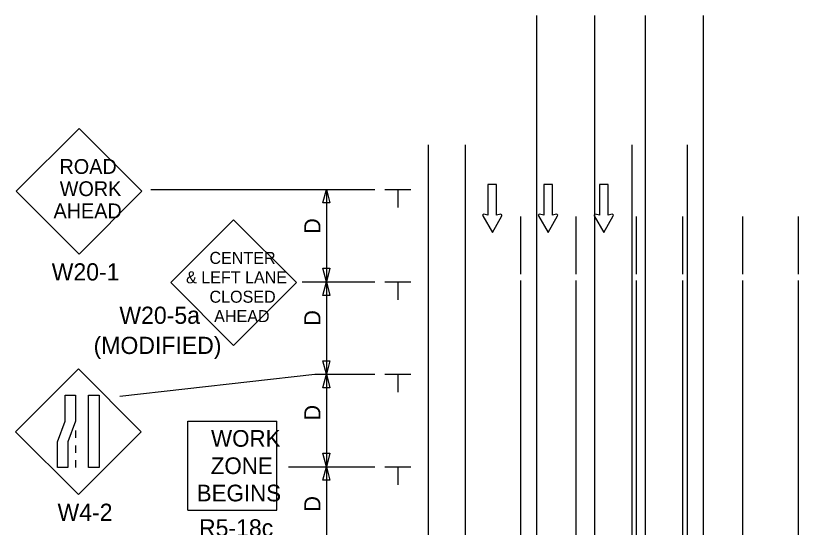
# Model space of a CAD drawing. Extents: x 16732 to 18475, y 6994 to 8262.
# Drawn here: x 16738 to 17076.3, y 8040.9 to 8262.3 of the extents above; entities that cross this region are included whole.
import ezdxf

# ---------------------------------------------------------------- set-up
doc = ezdxf.new("R2010")
doc.units = 0
for name, color, linetype in [('ALI_LEGAL_EX', 7, 'Continuous'), ('MT_SCRATCH_LEVEL_E', 7, 'Continuous'), ('PAVT_EDGE_EX', 7, 'Continuous'), ('TRAFFIC_SIGNS_PR', 7, 'Continuous'), ('TYPICAL_TEXT_DIMEN_PR', 7, 'Continuous')]:
    doc.layers.add(name, color=color, linetype=linetype)

msp = doc.modelspace()

# ---------------------------------------------------------------- linework, layer by layer
at = {"layer": 'ALI_LEGAL_EX'}
for p, q in [((16956.31, 7350.48), (16956.31, 8147.76)), ((16980.31, 7350.48), (16980.31, 8147.76)), ((17006.31, 7350.48), (17006.31, 8147.76)), ((17026.31, 7350.48), (17026.31, 8147.76)), ((17052.31, 7350.48), (17052.31, 8147.76)), ((17076.31, 7350.48), (17076.31, 8147.76))]:
    msp.add_line(p, q, dxfattribs=at)
for points in [[(16956.31, 8150.48), (16956.31, 8175.48)], [(16980.31, 8150.48), (16980.31, 8175.48)], [(17006.31, 8150.48), (17006.31, 8175.48)], [(17026.31, 8150.48), (17026.31, 8175.48)], [(17052.31, 8150.48), (17052.31, 8175.48)], [(17076.31, 8150.48), (17076.31, 8175.48)], [(16956.31, 8050.48), (16956.31, 8075.48)], [(16980.31, 8050.48), (16980.31, 8075.48)], [(17006.31, 8050.48), (17006.31, 8075.48)], [(17026.31, 8050.48), (17026.31, 8075.48)], [(17052.31, 8050.48), (17052.31, 8075.48)], [(17076.31, 8050.48), (17076.31, 8075.48)]]:
    msp.add_lwpolyline(points, dxfattribs=at)
at = {"layer": 'MT_SCRATCH_LEVEL_E'}
for p, q in [((16945.91, 8189.32), (16942.16, 8189.32)), ((16942.16, 8189.32), (16942.16, 8176.07)), ((16945.91, 8189.32), (16942.16, 8189.32)), ((16942.16, 8189.32), (16942.16, 8176.07)), ((16945.91, 8176.07), (16945.91, 8189.32)), ((16945.91, 8176.07), (16945.91, 8189.32)), ((16969.98, 8189.32), (16966.24, 8189.32)), ((16966.24, 8189.32), (16966.24, 8176.07)), ((16969.98, 8189.32), (16966.24, 8189.32)), ((16966.24, 8189.32), (16966.24, 8176.07)), ((16969.98, 8176.07), (16969.98, 8189.32)), ((16969.98, 8176.07), (16969.98, 8189.32)), ((16994.05, 8189.32), (16990.31, 8189.32)), ((16990.31, 8189.32), (16990.31, 8176.07)), ((16994.05, 8189.32), (16990.31, 8189.32)), ((16990.31, 8189.32), (16990.31, 8176.07)), ((16994.05, 8176.07), (16994.05, 8189.32)), ((16994.05, 8176.07), (16994.05, 8189.32)), ((16942.16, 8176.07), (16940.39, 8176.38)), ((16942.16, 8176.07), (16940.39, 8176.38)), ((16947.68, 8176.38), (16945.91, 8176.07)), ((16947.68, 8176.38), (16945.91, 8176.07)), ((16966.24, 8176.07), (16964.46, 8176.38)), ((16966.24, 8176.07), (16964.46, 8176.38)), ((16971.75, 8176.38), (16969.98, 8176.07)), ((16971.75, 8176.38), (16969.98, 8176.07)), ((16990.31, 8176.07), (16988.53, 8176.38)), ((16990.31, 8176.07), (16988.53, 8176.38)), ((16995.83, 8176.38), (16994.05, 8176.07)), ((16995.83, 8176.38), (16994.05, 8176.07)), ((16939.91, 8175.7), (16944.05, 8168.46)), ((16939.91, 8175.7), (16944.05, 8168.46)), ((16944.05, 8168.46), (16948.17, 8175.7)), ((16944.05, 8168.46), (16948.17, 8175.7)), ((16963.98, 8175.7), (16968.12, 8168.46)), ((16963.98, 8175.7), (16968.12, 8168.46)), ((16968.12, 8168.46), (16972.24, 8175.7)), ((16968.12, 8168.46), (16972.24, 8175.7)), ((16988.05, 8175.7), (16992.2, 8168.46)), ((16988.05, 8175.7), (16992.2, 8168.46)), ((16992.2, 8168.46), (16996.31, 8175.7)), ((16992.2, 8168.46), (16996.31, 8175.7))]:
    msp.add_line(p, q, dxfattribs=at)
for centre, start, end in [((16940.32, 8175.92), 80.0362, 209.7731), ((16940.32, 8175.92), 80.0362, 209.7731), ((16947.76, 8175.92), 330.4248, 99.9638), ((16947.76, 8175.92), 330.4248, 99.9638), ((16964.39, 8175.92), 80.0362, 209.7731), ((16964.39, 8175.92), 80.0362, 209.7731), ((16971.83, 8175.92), 330.4248, 99.9638), ((16971.83, 8175.92), 330.4248, 99.9638), ((16988.46, 8175.92), 80.0362, 209.7731), ((16988.46, 8175.92), 80.0362, 209.7731), ((16995.9, 8175.92), 330.4248, 99.9638), ((16995.9, 8175.92), 330.4248, 99.9638)]:
    msp.add_arc(centre, 0.463, start, end, dxfattribs=at)
at = {"layer": 'PAVT_EDGE_EX'}
for p, q in [((16963.15, 8262.34), (16963.15, 7433.15)), ((16988.15, 8262.34), (16988.15, 7433.15)), ((17010.15, 8262.34), (17010.15, 7433.15)), ((17035.15, 8262.34), (17035.15, 7433.15)), ((16916.31, 8206.5), (16916.31, 7425.05)), ((16932.31, 8206.5), (16932.31, 7425.05)), ((17004.31, 8206.5), (17004.31, 7350.48)), ((17028.31, 8206.5), (17028.31, 7350.48))]:
    msp.add_line(p, q, dxfattribs=at)
at = {"layer": 'TRAFFIC_SIGNS_PR'}
for p, q in [((16765.43, 8213.48), (16738.28, 8186.33)), ((16792.58, 8186.33), (16765.43, 8213.48)), ((16738.28, 8186.33), (16765.43, 8159.17)), ((16765.43, 8159.17), (16792.58, 8186.33)), ((16832.22, 8173.95), (16805.06, 8146.8)), ((16859.37, 8146.8), (16832.22, 8173.95)), ((16805.06, 8146.8), (16832.22, 8119.65)), ((16832.22, 8119.65), (16859.37, 8146.8)), ((16765.18, 8109.47), (16738.02, 8082.31)), ((16792.33, 8082.31), (16765.18, 8109.47)), ((16812.47, 8048.42), (16812.47, 8086.82)), ((16812.47, 8086.82), (16850.87, 8086.82)), ((16850.87, 8048.42), (16850.87, 8086.82)), ((16738.02, 8082.31), (16765.18, 8055.16)), ((16763.93, 8082.8), (16763.93, 8079.6)), ((16765.18, 8055.16), (16792.33, 8082.31)), ((16763.93, 8076.4), (16763.93, 8073.2)), ((16763.93, 8070), (16763.93, 8066.8)), ((16812.47, 8048.42), (16850.87, 8048.42))]:
    msp.add_line(p, q, dxfattribs=at)
for points in [[(16763.93, 8098.05), (16763.93, 8086.87), (16760.59, 8077.99), (16760.59, 8066.8), (16756.09, 8066.8), (16756.09, 8077.99), (16759.44, 8086.87), (16759.44, 8098.05)], [(16774.07, 8098.05), (16774.07, 8066.8), (16769.57, 8066.8), (16769.57, 8098.05)]]:
    msp.add_lwpolyline(points, close=True, dxfattribs=at)
at = {"layer": 'TYPICAL_TEXT_DIMEN_PR'}
for p, q in [((16796.49, 8187.14), (16893.31, 8187.14)), ((16870.74, 8181.27), (16872.31, 8187.14)), ((16872.31, 8187.14), (16872.31, 8147.14)), ((16872.31, 8187.14), (16873.88, 8181.27)), ((16897.56, 8187.14), (16908.81, 8187.14)), ((16903.18, 8187.14), (16903.18, 8179.35)), ((16872.31, 8181.27), (16870.74, 8181.27)), ((16873.88, 8181.27), (16872.31, 8181.27)), ((16872.31, 8147.14), (16870.74, 8153)), ((16870.74, 8153), (16872.31, 8153)), ((16872.31, 8153), (16873.88, 8153)), ((16873.88, 8153), (16872.31, 8147.14)), ((16861.91, 8147.14), (16893.31, 8147.14)), ((16867.31, 8147.14), (16893.31, 8147.14)), ((16870.74, 8141.27), (16872.31, 8147.14)), ((16872.31, 8147.14), (16872.31, 8107.14)), ((16872.31, 8147.14), (16873.88, 8141.27)), ((16897.56, 8147.14), (16908.81, 8147.14)), ((16903.18, 8147.14), (16903.18, 8139.35)), ((16872.31, 8141.27), (16870.74, 8141.27)), ((16873.88, 8141.27), (16872.31, 8141.27)), ((16872.31, 8107.14), (16870.74, 8113)), ((16870.74, 8113), (16872.31, 8113)), ((16872.31, 8113), (16873.88, 8113)), ((16873.88, 8113), (16872.31, 8107.14)), ((16783.12, 8097.72), (16867.31, 8107.14)), ((16867.31, 8107.14), (16893.31, 8107.14)), ((16870.74, 8101.27), (16872.31, 8107.14)), ((16872.31, 8107.14), (16872.31, 8067.14)), ((16872.31, 8107.14), (16873.88, 8101.27)), ((16897.56, 8107.14), (16908.81, 8107.14)), ((16903.18, 8107.14), (16903.18, 8099.35)), ((16872.31, 8101.27), (16870.74, 8101.27)), ((16873.88, 8101.27), (16872.31, 8101.27)), ((16872.31, 8067.14), (16870.74, 8073)), ((16870.74, 8073), (16872.31, 8073)), ((16872.31, 8073), (16873.88, 8073)), ((16873.88, 8073), (16872.31, 8067.14)), ((16855.96, 8067.14), (16893.31, 8067.14)), ((16867.31, 8067.14), (16893.31, 8067.14)), ((16870.74, 8061.27), (16872.31, 8067.14)), ((16872.31, 8067.14), (16872.31, 8027.14)), ((16872.31, 8067.14), (16873.88, 8061.27)), ((16897.56, 8067.14), (16908.81, 8067.14)), ((16903.18, 8067.14), (16903.18, 8059.35)), ((16872.31, 8061.27), (16870.74, 8061.27)), ((16873.88, 8061.27), (16872.31, 8061.27))]:
    msp.add_line(p, q, dxfattribs=at)

# ---------------------------------------------------------------- texts
at = {"layer": 'TRAFFIC_SIGNS_PR'}
for s, height, p in [('ROAD', 6.4, (16756.97, 8193.86)), ('WORK', 6.4, (16757.08, 8184.26)), ('AHEAD', 6.4, (16754.39, 8174.66)), ('CENTER', 5.2, (16821.79, 8154.91)), ('W20-1', 7.44, (16753.6, 8147.74)), ('& LEFT LANE', 5.2, (16811.66, 8146.51)), ('CLOSED', 5.2, (16821.8, 8138.11)), ('W20-5a', 7.44, (16782.85, 8128.98)), ('AHEAD', 5.2, (16823.82, 8129.71)), ('(MODIFIED)', 7.44, (16771.71, 8115.94)), ('WORK', 7.217, (16822.47, 8075.79)), ('ZONE', 7.217, (16822.35, 8063.98)), ('BEGINS', 7.217, (16816.28, 8052.17)), ('W4-2', 7.44, (16756.13, 8043.72)), ('R5-18c', 7.44, (16817.28, 8036.98))]:
    msp.add_text(s, height=height, dxfattribs=at).set_placement(p)
at = {"layer": 'TYPICAL_TEXT_DIMEN_PR'}
for p in [(16869.75, 8167.9), (16869.75, 8128.16), (16869.75, 8087.13), (16869.75, 8047.72)]:
    msp.add_text('D', height=7, rotation=90, dxfattribs=at).set_placement(p)

doc.saveas('drawing.dxf')
